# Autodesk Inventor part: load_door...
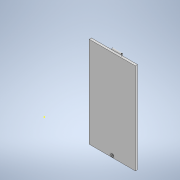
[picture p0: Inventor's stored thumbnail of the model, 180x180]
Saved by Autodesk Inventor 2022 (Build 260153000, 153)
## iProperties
Created: 2021-07
Part Number: load_door...
Material: Generic
Document SubType Name: Modeling
Designer: Hp
Density: 1 g/cm^3
Appearance: Default
Author: Hp
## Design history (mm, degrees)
sketch "Sketch1"
  geometry: L1 (0, 0)-(687.359, 0); L2 (687.359, 0)-(687.359, 600); L3 (687.359, 600)-(0, 600); L4 (0, 600)-(0, 0)
  constraints: 8 end point, 2 parallel, 1 horizontal, 1 perpendicular
  dimensions: "d0" = 687.359 distance of L3.end L2.end; "d1" = 600 distance of L2.end L1.end
extrude "Extrusion1" new body sketch "Sketch1" distance "d2" = 50; taper "d3" = 0 deg
sketch "Sketch2"
  geometry: L1 (608.519, 0.168)-(606.519, 0.168); L2 (606.519, 0.168)-(606.519, -4.832); L3 (606.519, -4.832)-(608.519, -4.832); L4 (608.519, -4.832)-(608.519, 0.168); L5 (687.359, 0)-(687.359, -50) reference; L6 (0, 0)-(0, -50) reference; L7 (99.852, 0)-(101.852, 0); L8 (101.852, 0)-(101.852, -5); L9 (101.852, -5)-(99.852, -5); L10 (99.852, -5)-(99.852, 0)
  constraints: 16 end point, 4 parallel, 2 horizontal, 2 perpendicular
  dimensions: "d4" = 2 distance of L3.end L2.end; "d5" = 5 distance of L2.end L1.end; "d6" = 78.84 distance between parallel lines of L4 L5; "d7" = 2 distance of L8.end L9.end; "d8" = 5 distance of L7.end L8.end; "d9" = 99.852 distance between parallel lines of L10 L6
extrude "Extrusion2" join sketch "Sketch2" distance "d10" = 13; taper "d11" = 0 deg
node "Sketch3"
sketch "Sketch4"
  geometry: 1 further point
sketch "Sketch6"
  geometry: C1 r 5 at (2.181, 10.483); 1 further point
  constraints: 1 centre point
  dimensions: "d16" = 10 diameter of C1
extrude "Extrusion4" join sketch "Sketch6" distance "d17" = 60; taper "d18" = 0 deg
sketch "Sketch7"
  geometry: L1 (0, 600)-(50, 600) reference; L2 (0, 0)-(50, 0) reference; L3 (50, 600)-(14.505, 600); L4 (14.505, 600)-(14.505, 0); L5 (14.505, 0)-(50, 0); L6 (50, 0)-(50, 600); 2 further points
  constraints: 8 end point, 2 parallel, 1 horizontal, 1 perpendicular, 1 point on line
extrude "Extrusion5" cut sketch "Sketch7" distance "d19" = 700; taper "d20" = 0 deg
sketch "Sketch8"
  geometry: L1 (0, 0)-(-14.505, 0) reference; L2 (0, 600)-(0, 0) reference; L3 (-14.505, 0)-(0, 0); L4 (0, 0)-(0, 14.773); L5 (0, 14.773)-(-14.505, 14.773); L6 (-14.505, 14.773)-(-14.505, 0)
  constraints: 8 end point, 2 parallel, 1 horizontal, 1 perpendicular, 1 point on line
extrude "Extrusion6" cut sketch "Sketch8" distance "d21" = 700; taper "d22" = 0 deg
sketch "Sketch9"
  geometry: L1 (-587.507, 0)-(-687.359, 0) reference; L2 (-687.359, 14.505)-(0, 14.505) reference; L3 (-687.359, 0)-(-680.987, 0); L4 (-680.987, 0)-(-680.987, 14.505); L5 (-680.987, 14.505)-(-687.359, 14.505); L6 (-687.359, 14.505)-(-687.359, 0); 2 further points
  constraints: 8 end point, 2 parallel, 1 horizontal, 1 perpendicular, 1 point on line
extrude "Extrusion7" cut sketch "Sketch9" distance "d23" = 700; taper "d24" = 0 deg
sketch "Sketch11"
  geometry: L1 (-350.987, 0)-(-350.987, -40) reference; L2 (-320.987, 0)-(-320.987, -40) reference; L3 (-320.987, -40)-(-350.987, -40) reference; C1 r 10 at (-335.987, -27)
  constraints: 1 centre point
  dimensions: "d29" = 20 diameter of C1; "d30" = 15 distance from line of C1.centre L1; "d31" = 15 distance from line of C1.centre L2 (derived); "d32" = 13 distance from line of C1.centre L3
extrude "Extrusion9" cut sketch "Sketch11" distance "d33" = 40; taper "d34" = 0 deg
sketch "Sketch12"
  geometry: L1 (0, 14.505)-(680.987, 14.505) reference; L2 (0, 0)-(380.987, 0); L3 (380.987, 0)-(380.987, 14.505); L4 (380.987, 14.505)-(0, 14.505); L5 (0, 14.505)-(0, 0); L6 (680.987, 14.505)-(680.987, 0) reference; 4 further points
  constraints: 8 end point, 2 parallel, 1 horizontal, 1 perpendicular, 1 point on line
  dimensions: "d35" = 300 distance between parallel lines of L6 L3
extrude "Extrusion10" cut sketch "Sketch12" extent not by distance; stored distance "d36" = 0; taper "d37" = 0 deg
sketch "Sketch13"
  geometry: L1 (14.505, -585.227)-(14.505, 0) reference; L2 (14.505, -585.227)-(0, -585.227); L3 (0, -585.227)-(0, 0); L4 (0, 0)-(14.505, 0); L5 (14.505, 0)-(14.505, -585.227); 2 further points
  constraints: 8 end point, 2 parallel, 1 horizontal, 1 perpendicular
extrude "Extrusion11" join sketch "Sketch13" distance "d38" = 19.87; taper "d39" = 0 deg
sketch "Sketch14"
  geometry: L1 (14.505, 585.227)-(14.505, 0) reference; L2 (0, 0)-(0, 585.227) reference; L3 (14.505, 0)-(0, 0); L4 (0, 0)-(0, 585.227); L5 (0, 585.227)-(14.505, 585.227); L6 (14.505, 585.227)-(14.505, 0); 3 further points
  constraints: 8 end point, 2 parallel, 1 horizontal, 1 perpendicular
extrude "Extrusion12" cut sketch "Sketch14" distance "d40" = 19.87; taper "d41" = 0 deg
sketch "Sketch15"
  geometry: L1 (0, 0)-(-300, 0) reference; L2 (-300, 14.505)-(0, 14.505) reference; L3 (0, 0)-(-300, 0); L4 (-300, 0)-(-300, 14.505); L5 (-300, 14.505)-(0, 14.505); L6 (0, 14.505)-(0, 0); 3 further points
  constraints: 8 end point, 2 parallel, 1 horizontal, 1 perpendicular
extrude "Extrusion13" join sketch "Sketch15" distance "d42" = 6.625; taper "d43" = 0 deg
sketch "Sketch17"
  geometry: L1 (-407.229, 8.148)-(-407.229, 600) reference; L2 (-407.229, 8.148)-(-707.229, 8.148) reference; C1 r 10 at (-557.229, 20.648); 1 further point
  constraints: 1 centre point
  dimensions: "d49" = 20 diameter of C1; "d50" = 150 distance from line of L1 C1.centre; "d51" = 12.5 distance from line of L2 C1.centre
extrude "Extrusion15" cut sketch "Sketch17" extent not by distance; stored distance "d52" = 0; taper "d53" = 0 deg
body "Solid1"
